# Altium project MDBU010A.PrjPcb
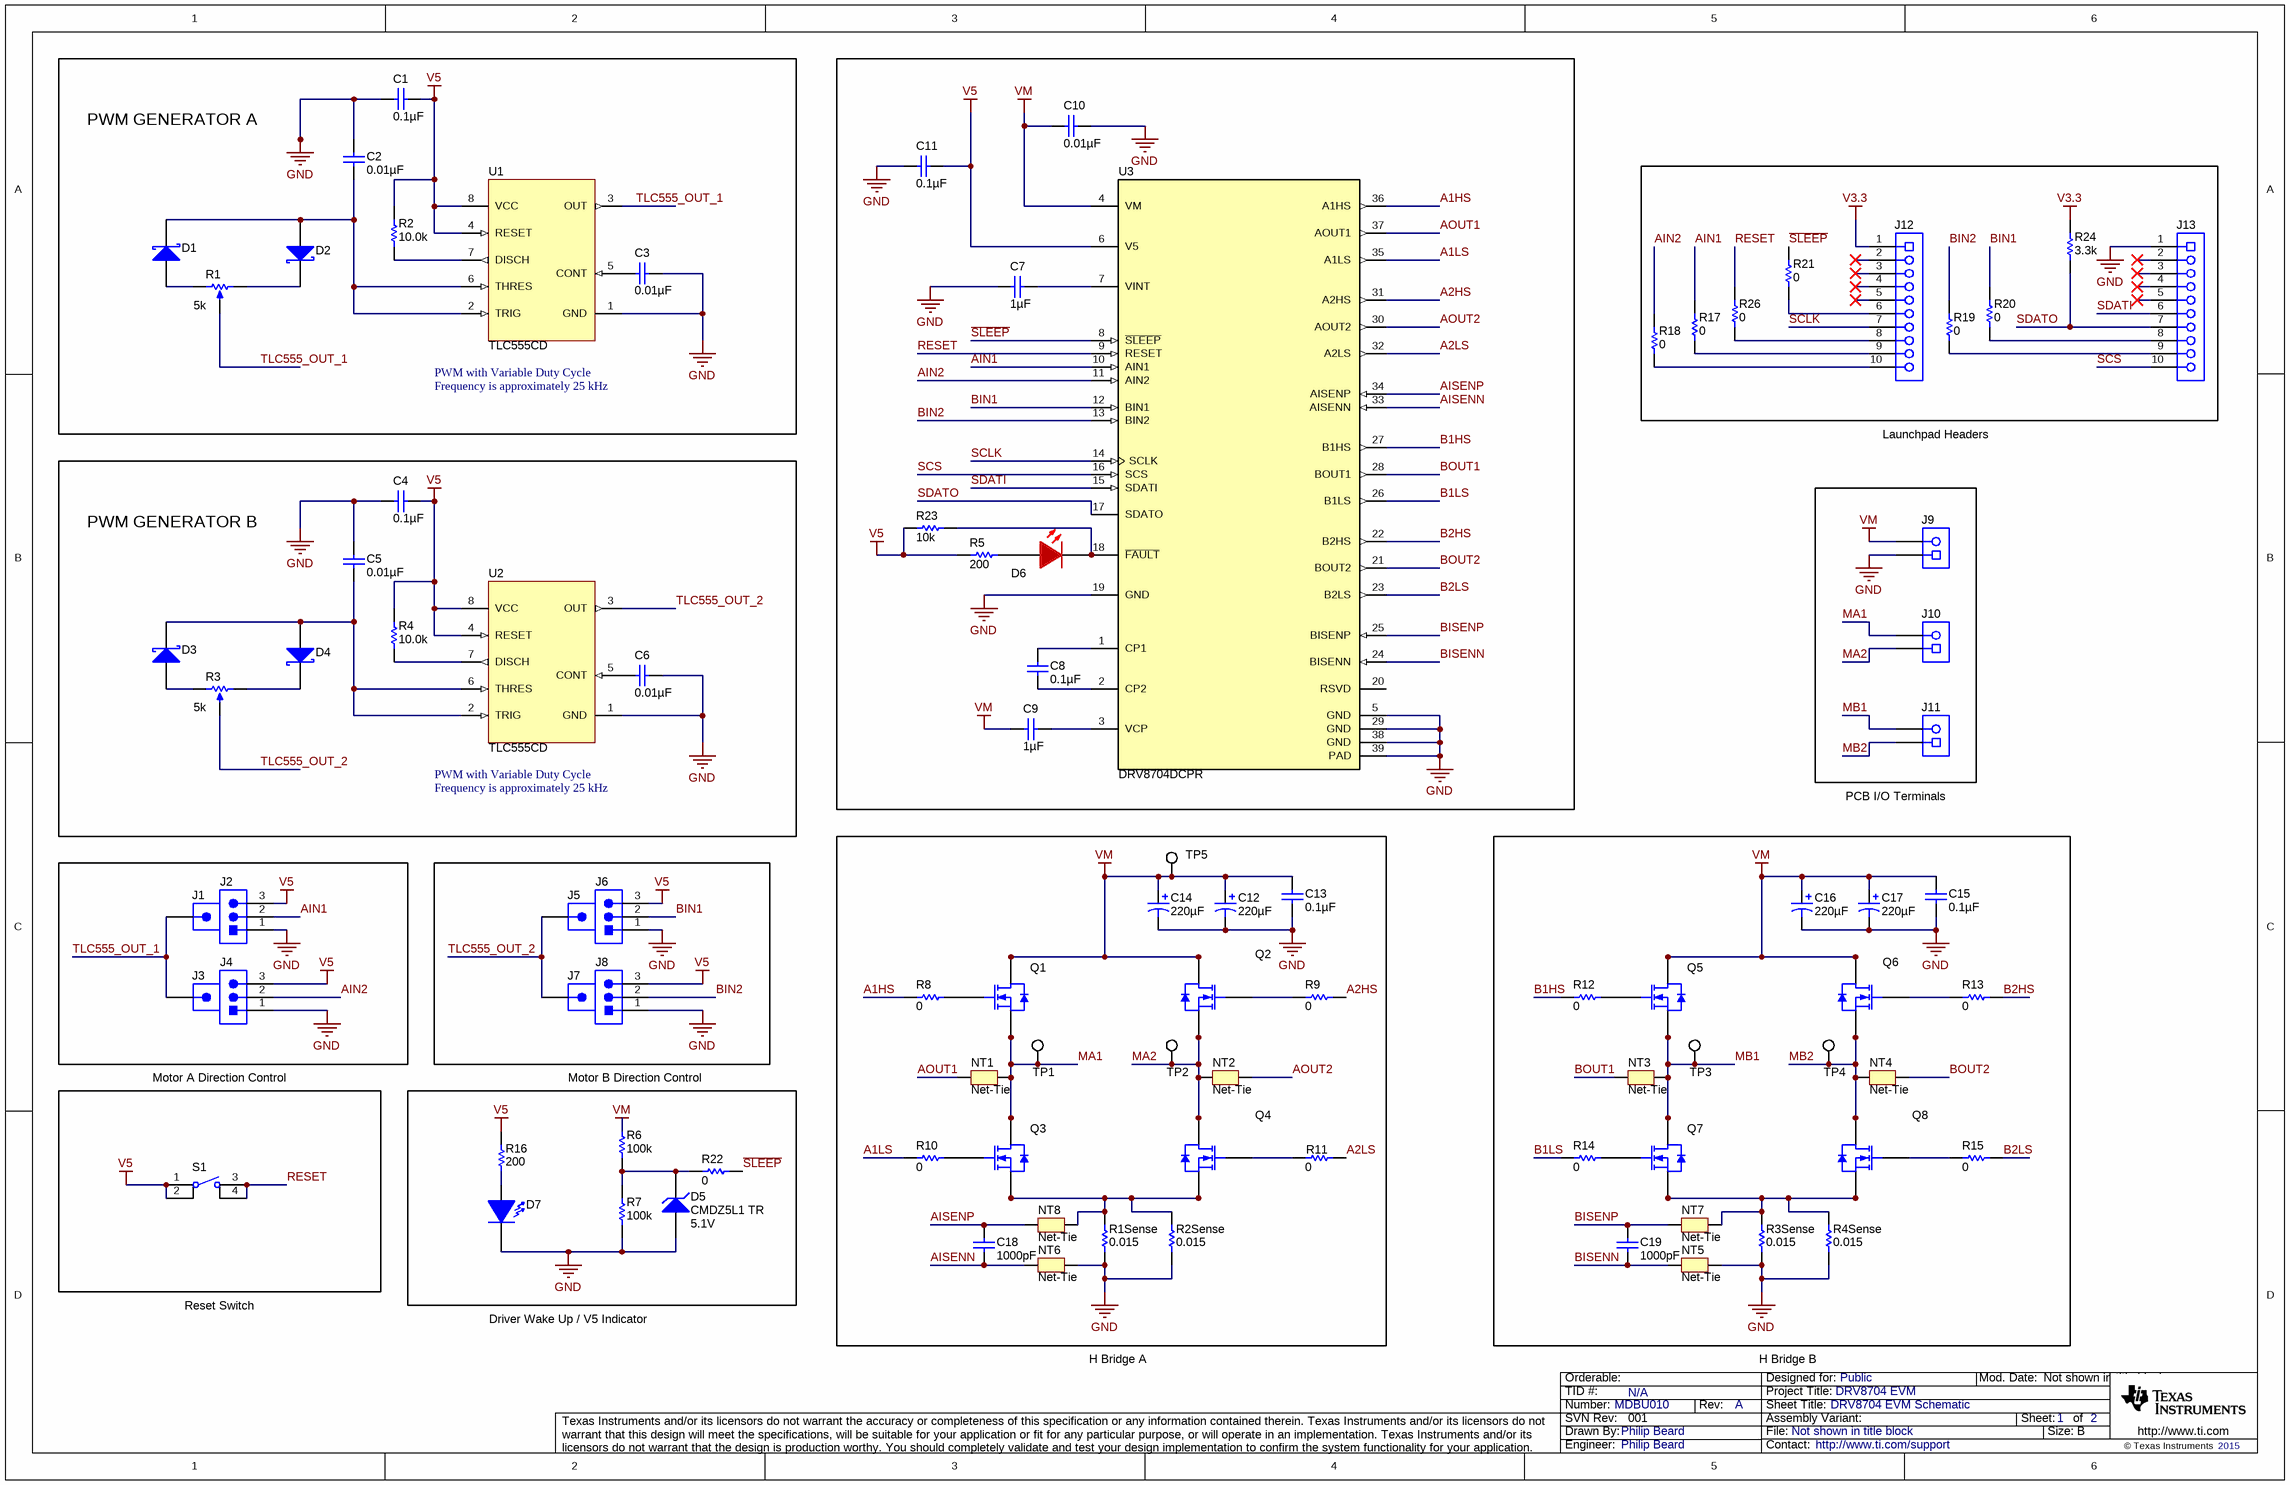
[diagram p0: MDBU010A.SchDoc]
CopyrightYear: 2015; PCB_Layout: Philip Beard; PCB_Rev: A; PRJ_Customer: Public; PRJ_Engineer: Philip Beard; PRJ_Number: MDBU010; PRJ_Title: DRV8704 EVM; SCH_Rev: A; TechSupport: http://www.ti.com/support; TID: N/A
2 sheets, 106 parts. Net scope: global (net labels, ports and power ports of the same name join across sheets).
Board file: MDBU010A.PcbDoc
Sheets:
  MDBU010A.SchDoc
  MDBU010A_Hardware.SchDoc

## Sheet MDBU010A.SchDoc: DRV8704 EVM Schematic
size 431 x 279 mm; VersionControl_RevNumber: 001; Date: Not shown in title block; ApprovedBy: Not shown in title block; CheckedBy: Not shown in title block; Author: Not shown in title block; CompanyName: Not shown in title block; DrawnBy: Philip Beard; Engineer: Not shown in title block; Organization: Not shown in title block; Address1: Not shown in title block; Address2: Not shown in title block; Address3: Not shown in title block; Address4: Not shown in title block; DocumentNumber: 001; Revision: Use project parameter SCH_Rev; SheetNumber: 1; SheetTotal: 2; PageSetup: Record=PageOptions¦CenterHorizontal=True¦CenterVertical=True¦PrintScale=1.00¦XCorrection=1.00¦YCorrection=1.00¦PrintKind=0¦BorderSize=5000000¦LeftOffset=0¦BottomOffset=0¦Orientation=2¦PaperLength=1000¦PaperWidth=1000¦Scale=100¦PaperSource=15¦PrintQuality=600¦MediaType=1¦DitherType=10¦PaperKind=Letter¦PrintScaleMode=1

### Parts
C1  ValueDisplayed: 0.1µF  [0603L]  (hidden comment: C0603C104M4RACTU)
C2  ValueDisplayed: 0.01µF  [0402L]  (hidden comment: GCM155R71E103KA37D)
C3  ValueDisplayed: 0.01µF  [0603L]  (hidden comment: C0603X103K5RACTU)
C4  ValueDisplayed: 0.1µF  [0603L]  (hidden comment: C0603C104M4RACTU)
C5  ValueDisplayed: 0.01µF  [0402L]  (hidden comment: GCM155R71E103KA37D)
C6  ValueDisplayed: 0.01µF  [0603L]  (hidden comment: C0603X103K5RACTU)
C7  ValueDisplayed: 1µF  [0603L]  (hidden comment: EMK107B7105KA-T)
C8  ValueDisplayed: 0.1µF  [0805_HV]  (hidden comment: GRM21BR71H104KA01L)
C9  ValueDisplayed: 1µF  [0402L]  (hidden comment: EMK105BJ105KVHF)
C10  ValueDisplayed: 0.01µF  [0402L]  (hidden comment: C0402C103J5RACTU)
C11  ValueDisplayed: 0.1µF  [0402L]  (hidden comment: GRM155R61A104KA01D)
C12  ValueDisplayed: 220µF  [SM_RADIAL_H13]  (hidden comment: EEE-TK1J221AQ)
C13  ValueDisplayed: 0.1µF  [0402L]  (hidden comment: C1005X7R1H104K050BB)
C14  ValueDisplayed: 220µF  [SM_RADIAL_H13]  (hidden comment: EEE-TK1J221AQ)
C15  ValueDisplayed: 0.1µF  [0402L]  (hidden comment: C1005X7R1H104K050BB)
C16  ValueDisplayed: 220µF  [SM_RADIAL_H13]  (hidden comment: EEE-TK1J221AQ)
C17  ValueDisplayed: 220µF  [SM_RADIAL_H13]  (hidden comment: EEE-TK1J221AQ)
C18  ValueDisplayed: 1000pF  [0402L]  (hidden comment: C1005C0G1E102J)
C19  ValueDisplayed: 1000pF  [0402L]  (hidden comment: C1005C0G1E102J)
D1  MSS1P4-M3/89A  [MicroSMP]  (value not drawn)
D2  MSS1P4-M3/89A  [MicroSMP]  (value not drawn)
D3  MSS1P4-M3/89A  [MicroSMP]  (value not drawn)
D4  MSS1P4-M3/89A  [MicroSMP]  (value not drawn)
D5  CMDZ5L1 TR  value 5.1V  [sod-323]
D6  150080SS75000  [WL-SMCW_RED_0805]  (value not drawn)
D7  150060VS75000  [WL-SMCW_GREEN]  (value not drawn)
J1  PEC01SAAN  [Sullins_PEC01SAAN]  (value not drawn)
J2  PEC03SAAN  [CONN_PEC03SAAN]  (value not drawn)
J3  PEC01SAAN  [Sullins_PEC01SAAN]  (value not drawn)
J4  PEC03SAAN  [CONN_PEC03SAAN]  (value not drawn)
J5  PEC01SAAN  [Sullins_PEC01SAAN]  (value not drawn)
J6  PEC03SAAN  [CONN_PEC03SAAN]  (value not drawn)
J7  PEC01SAAN  [Sullins_PEC01SAAN]  (value not drawn)
J8  PEC03SAAN  [CONN_PEC03SAAN]  (value not drawn)
J9  691 101 710 002  [Wurth_691101710002]  (value not drawn)
J10  691 101 710 002  [Wurth_691101710002]  (value not drawn)
J11  691 101 710 002  [Wurth_691101710002]  (value not drawn)
J12  SSW-110-23-F-S  [CONN_SSW-110-23-F-S]  (value not drawn)
J13  SSW-110-23-F-S  [CONN_SSW-110-23-F-S]  (value not drawn)
NT1  Net-Tie  [Net-Tie_10milWide_30milLong]  (net tie, no BOM)
NT2  Net-Tie  [Net-Tie_10milWide_30milLong]  (net tie, no BOM)
NT3  Net-Tie  [Net-Tie_10milWide_30milLong]  (net tie, no BOM)
NT4  Net-Tie  [Net-Tie_10milWide_30milLong]  (net tie, no BOM)
NT5  Net-Tie  [Net-Tie_10milWide_30milLong]  (net tie, no BOM)
NT6  Net-Tie  [Net-Tie_10milWide_30milLong]  (net tie, no BOM)
NT7  Net-Tie  [Net-Tie_10milWide_30milLong]  (net tie, no BOM)
NT8  Net-Tie  [Net-Tie_10milWide_30milLong]  (net tie, no BOM)
Q1  CSD18540Q5B  [TRANS_NexFET_Q5B]  (value not drawn)
Q2  CSD18540Q5B  [TRANS_NexFET_Q5B]  (value not drawn)
Q3  CSD18540Q5B  [TRANS_NexFET_Q5B]  (value not drawn)
Q4  CSD18540Q5B  [TRANS_NexFET_Q5B]  (value not drawn)
Q5  CSD18540Q5B  [TRANS_NexFET_Q5B]  (value not drawn)
Q6  CSD18540Q5B  [TRANS_NexFET_Q5B]  (value not drawn)
Q7  CSD18540Q5B  [TRANS_NexFET_Q5B]  (value not drawn)
Q8  CSD18540Q5B  [TRANS_NexFET_Q5B]  (value not drawn)
R1  value 5k  [BOURNS_3386P]  (hidden comment: 3386P-1-502LF)
R1Sense  ValueDisplayed: 0.015  [2512]  (hidden comment: CSRN2512FK15L0)
R2  ValueDisplayed: 10.0k  [0603L]  (hidden comment: ERJ-3EKF1002V)
R2Sense  ValueDisplayed: 0.015  [2512]  (hidden comment: CSRN2512FK15L0)
R3  value 5k  [BOURNS_3386P]  (hidden comment: 3386P-1-502LF)
R3Sense  ValueDisplayed: 0.015  [2512]  (hidden comment: CSRN2512FK15L0)
R4  ValueDisplayed: 10.0k  [0603L]  (hidden comment: ERJ-3EKF1002V)
R4Sense  ValueDisplayed: 0.015  [2512]  (hidden comment: CSRN2512FK15L0)
R5  ValueDisplayed: 200  [0402L]  (hidden comment: CRCW0402200RFKED)
R6  ValueDisplayed: 100k  [0402L]  (hidden comment: CRCW0402100KJNED)
R7  ValueDisplayed: 100k  [0402L]  (hidden comment: CRCW0402100KJNED)
R8  ValueDisplayed: 0  [0402L]  (hidden comment: CRCW04020000Z0ED)
R9  ValueDisplayed: 0  [0402L]  (hidden comment: CRCW04020000Z0ED)
R10  ValueDisplayed: 0  [0402L]  (hidden comment: CRCW04020000Z0ED)
R11  ValueDisplayed: 0  [0402L]  (hidden comment: CRCW04020000Z0ED)
R12  ValueDisplayed: 0  [0402L]  (hidden comment: CRCW04020000Z0ED)
R13  ValueDisplayed: 0  [0402L]  (hidden comment: CRCW04020000Z0ED)
R14  ValueDisplayed: 0  [0402L]  (hidden comment: CRCW04020000Z0ED)
R15  ValueDisplayed: 0  [0402L]  (hidden comment: CRCW04020000Z0ED)
R16  ValueDisplayed: 200  [0402L]  (hidden comment: CRCW0402200RFKED)
R17  ValueDisplayed: 0  [0402L]  (hidden comment: CRCW04020000Z0ED)
R18  ValueDisplayed: 0  [0402L]  (hidden comment: CRCW04020000Z0ED)
R19  ValueDisplayed: 0  [0402L]  (hidden comment: CRCW04020000Z0ED)
R20  ValueDisplayed: 0  [0402L]  (hidden comment: CRCW04020000Z0ED)
R21  ValueDisplayed: 0  [0402L]  (hidden comment: CRCW04020000Z0ED)
R22  ValueDisplayed: 0  [0402L]  (hidden comment: CRCW04020000Z0ED)
R23  ValueDisplayed: 10k  [0402L]  (hidden comment: CRCW040210K0JNED)
R24  ValueDisplayed: 3.3k  [0402L]  (hidden comment: CRCW04023K30JNED)
R26  ValueDisplayed: 0  [0402L]  (hidden comment: CRCW04020000Z0ED)
S1  4-1437565-1  [SW_FSM4JSMA]  (value not drawn)
TP1  5016  [Testpoint_Keystone_Compact]  (value not drawn)
TP2  5016  [Testpoint_Keystone_Compact]  (value not drawn)
TP3  5016  [Testpoint_Keystone_Compact]  (value not drawn)
TP4  5016  [Testpoint_Keystone_Compact]  (value not drawn)
TP5  5016  [Testpoint_Keystone_Compact]  (value not drawn)
U1  TLC555CD  [D0008A_L]
U2  TLC555CD  [D0008A_L]
U3  DRV8704DCPR  [DCP0038A_N]

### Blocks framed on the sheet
PWM GENERATOR A: C1-C3 D1 D2 R1 R2 U1
PWM GENERATOR B: C4-C6 D3 D4 R3 R4 U2
Motor A Direction Control: S1
Motor B Direction Control: D5 D7 R6 R7 R16 R22

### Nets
GND: C1.1 C2.1 C3.1 C4.1 C5.1 C6.1 C7.2 C10.1 C11.2 C12.2(-) C13.2 C14.2(-) C15.2 C16.2(-) C17.2(-) D5.2(A) D7.1(K) J2.1 J4.1 J6.1 J8.1 J9.1 J13.1 NT5.2 NT6.2 R1Sense.1 R2Sense.1 R3Sense.1 R4Sense.1 R7.1 U1.1(GND) U2.1(GND) U3.5(GND) U3.19(GND) U3.29(GND) U3.38(GND) U3.39(PAD)
V3.3: J12.1 R24.2
V5: C1.2 C4.2 C11.1 J2.3 J4.3 J6.3 J8.3 R2.2 R4.2 R5.1 R16.2 R23.2 S1.1 S1.2 U1.4(RESET) U1.8(VCC) U2.4(RESET) U2.8(VCC) U3.6(V5)
VM: C9.2 C10.2 C12.1(+) C13.1 C14.1(+) C15.1 C16.1(+) C17.1(+) J9.2 Q1.5(D) Q1.6(D) Q1.7(D) Q1.8(D) Q2.5(D) Q2.6(D) Q2.7(D) Q2.8(D) Q5.5(D) Q5.6(D) Q5.7(D) Q5.8(D) Q6.5(D) Q6.6(D) Q6.7(D) Q6.8(D) R6.2 TP5.1 U3.4(VM)
~{SLEEP}: R21.2 R22.1 U3.8(~{SLEEP})
A1HS: R8.1 U3.36(A1HS)
A1LS: R10.1 U3.35(A1LS)
A2HS: R9.2 U3.31(A2HS)
A2LS: R11.2 U3.32(A2LS)
AIN1: J2.2 R17.2 U3.10(AIN1)
AIN2: J4.2 R18.2 U3.11(AIN2)
AISENN: C18.2 NT6.1 U3.33(AISENN)
AISENP: C18.1 NT8.1 U3.34(AISENP)
AOUT1: NT1.1 U3.37(AOUT1)
AOUT2: NT2.2 U3.30(AOUT2)
B1HS: R12.1 U3.27(B1HS)
B1LS: R14.1 U3.26(B1LS)
B2HS: R13.2 U3.22(B2HS)
B2LS: R15.2 U3.23(B2LS)
BIN1: J6.2 R20.2 U3.12(BIN1)
BIN2: J8.2 R19.2 U3.13(BIN2)
BISENN: C19.2 NT5.1 U3.24(BISENN)
BISENP: C19.1 NT7.1 U3.25(BISENP)
BOUT1: NT3.1 U3.28(BOUT1)
BOUT2: NT4.2 U3.21(BOUT2)
MA1: J10.2 NT1.2 Q1.1(S) Q1.2(S) Q1.3(S) Q3.5(D) Q3.6(D) Q3.7(D) Q3.8(D) TP1.1
MA2: J10.1 NT2.1 Q2.1(S) Q2.2(S) Q2.3(S) Q4.5(D) Q4.6(D) Q4.7(D) Q4.8(D) TP2.1
MB1: J11.2 NT3.2 Q5.1(S) Q5.2(S) Q5.3(S) Q7.5(D) Q7.6(D) Q7.7(D) Q7.8(D) TP3.1
MB2: J11.1 NT4.1 Q6.1(S) Q6.2(S) Q6.3(S) Q8.5(D) Q8.6(D) Q8.7(D) Q8.8(D) TP4.1
RESET: R26.2 S1.3 S1.4 U3.9(RESET)
SCLK: J12.7 U3.14(SCLK)
SCS: J13.10 U3.16(SCS)
SDATI: J13.6 U3.15(SDATI)
SDATO: J13.7 R24.1 U3.17(SDATO)
TLC555_OUT_1: J1.1 J3.1 R1.2(WIPER) U1.3(OUT)
TLC555_OUT_2: J5.1 J7.1 R3.2(WIPER) U2.3(OUT)
NetC2_2: C2.2 D1.1(K) D2.2(A) U1.2(TRIG) U1.6(THRES)
NetC3_2: C3.2 U1.5(CONT)
NetC5_2: C5.2 D3.1(K) D4.2(A) U2.2(TRIG) U2.6(THRES)
NetC6_2: C6.2 U2.5(CONT)
NetC7_1: C7.1 U3.7(VINT)
NetC8_1: C8.1 U3.2(CP2)
NetC8_2: C8.2 U3.1(CP1)
NetC9_1: C9.1 U3.3(VCP)
NetD1_2: D1.2(A) R1.1(CCW)
NetD2_1: D2.1(K) R1.3(CW)
NetD3_2: D3.2(A) R3.1(CCW)
NetD4_1: D4.1(K) R3.3(CW)
NetD5_1: D5.1(K) R6.1 R7.2 R22.2
NetD6_1: D6.1(K) R23.1 U3.18(~{FAULT})
NetD6_2: D6.2(A) R5.2
NetD7_2: D7.2(A) R16.1
NetJ12_6: J12.6 R21.1
NetJ12_8: J12.8 R26.1
NetJ12_9: J12.9 R17.1
NetJ12_10: J12.10 R18.1
NetJ13_8: J13.8 R20.1
NetJ13_9: J13.9 R19.1
NetNT7_2: NT7.2 Q7.1(S) Q7.2(S) Q7.3(S) Q8.1(S) Q8.2(S) Q8.3(S) R3Sense.2 R4Sense.2
NetNT8_2: NT8.2 Q3.1(S) Q3.2(S) Q3.3(S) Q4.1(S) Q4.2(S) Q4.3(S) R1Sense.2 R2Sense.2
NetQ1_4: Q1.4(G) R8.2
NetQ2_4: Q2.4(G) R9.1
NetQ3_4: Q3.4(G) R10.2
NetQ4_4: Q4.4(G) R11.1
NetQ5_4: Q5.4(G) R12.2
NetQ6_4: Q6.4(G) R13.1
NetQ7_4: Q7.4(G) R14.2
NetQ8_4: Q8.4(G) R15.1
NetR2_1: R2.1 U1.7(DISCH)
NetR4_1: R4.1 U2.7(DISCH)

Not connected (* = marked no-connect by the designer): J12 2* 3* 4* 5*; J13 2* 3* 4* 5*; U3 20(RSVD)

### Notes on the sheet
- PWM with Variable Duty Cycle
- Frequency is approximately 25 kHz
- Launchpad Headers
- (near J11) PCB I/O Terminals
- Reset Switch
- Driver Wake Up / V5 Indicator
- H Bridge A
- H Bridge B

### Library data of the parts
C1 C4 = C0603C104M4RACTU: CAP, CERM, 0.1 µF, 16 V, +/- 20%, X7R, 0603; Manufacturer: Kemet; Value: 0.1uF; Polarized: N; CompType: Capacitor; U/M: EA; Cap_F: 0.0000001; Tolerance_%: 20; Value1: Unknown; VDC_V: 16; Value2: 16V; TaMin_C: -55; TaMax_C: 125; Cap_Case: 0603
C2 C5 = GCM155R71E103KA37D: CAP, CERM, 0.01 µF, 25 V, +/- 10%, X7R, 0402; Manufacturer: MuRata; Value: 0.01uF; Polarized: N; CompType: Capacitor; U/M: EA; Cap_F: 0.00000001; Tolerance_%: 10; Value1: Unknown; VDC_V: 25; Value2: 25V; TaMin_C: -55; TaMax_C: 125; Cap_Case: 0402; AEC Category: Q200
C3 C6 = C0603X103K5RACTU: CAP, CERM, 0.01 µF, 50 V, +/- 10%, X7R, 0603; Manufacturer: Kemet; Value: 0.01uF; Polarized: N; CompType: Capacitor; U/M: EA; Cap_F: 0.00000001; Tolerance_%: 10; Value1: Unknown; VDC_V: 50; Value2: 50V; TaMin_C: -55; TaMax_C: 125; Cap_Case: 0603
C7 = EMK107B7105KA-T: CAP, CERM, 1 µF, 16 V, +/- 10%, X7R, 0603; Manufacturer: Taiyo Yuden; Polarized: N; CompType: Capacitor; Value: 1uF; U/M: EA; Cap_F: 0.000001; Tolerance_%: 10; Value1: Unknown; VDC_V: 16; Value2: 16V; TaMin_C: -55; TaMax_C: 85; Cap_Case: 0603; AEC Category: Q200
C8 = GRM21BR71H104KA01L: CAP, CERM, 0.1 µF, 50 V, +/- 10%, X7R, 0805; Manufacturer: MuRata; Polarized: N; CompType: Capacitor; Value: 0.1uF; U/M: EA; Cap_F: 0.0000001; Tolerance_%: 10; Value1: Unknown; VDC_V: 50; Value2: 50V; TaMin_C: -55; TaMax_C: 125; Cap_Case: 0805; AEC Category: Q200
C9 = EMK105BJ105KVHF: CAP, CERM, 1 µF, 16 V, +/- 10%, X5R, 0402; Manufacturer: Taiyo Yuden; Polarized: N; CompType: Capacitor; Value: 1uF; U/M: EA; Cap_F: 0.000001; Tolerance_%: 10; Value1: Unknown; VDC_V: 16; Value2: 16V; TaMin_C: -55; TaMax_C: 85; Cap_Case: 0402; AEC Category: Q200
C10 = C0402C103J5RACTU: CAP, CERM, 0.01 µF, 50 V, +/- 5%, X7R, 0402; Manufacturer: Kemet; Polarized: N; CompType: Capacitor; Value: 0.01uF; U/M: EA; Cap_F: 0.00000001; Tolerance_%: 5; Value1: Unknown; VDC_V: 50; Value2: 50V; TaMin_C: -55; TaMax_C: 125; Cap_Case: 0402; AEC Category: Q200
C11 = GRM155R61A104KA01D: CAP, CERM, 0.1 µF, 10 V, +/- 10%, X5R, 0402; Manufacturer: MuRata; Polarized: N; CompType: Capacitor; Value: 0.1uF; U/M: EA; Cap_F: 0.0000001; Tolerance_%: 10; Value1: Unknown; Value2: 10V; TaMin_C: -55; TaMax_C: 85; Cap_Case: 0402; AEC Category: Q200
C12 C14 C16 C17 = EEE-TK1J221AQ: CAP, AL, 220 µF, 63 V, +/- 20%, 0.26 ohm, AEC-Q200 Grade 1, SMD; Manufacturer: Panasonic; Polarized: Y; CompType: Capacitor; Value: 220uF; U/M: EA; Cap_F: 0.00022; Tolerance_%: 20; VDC_V: 63; Value2: 63V; ESR_ohm: 0.26; IRMS_A: 0.35; TaMin_C: -40; TaMax_C: 125; Cap_Case: 12.5x13.5; AEC Category: Q200; AEC Grade: 1
C13 C15 = C1005X7R1H104K050BB: CAP, CERM, 0.1 µF, 50 V, +/- 10%, X7R, 0402; Manufacturer: TDK; Polarized: N; CompType: Capacitor; Value: 0.1uF; U/M: EA; Cap_F: 0.0000001; Tolerance_%: 10; Value1: Unknown; VDC_V: 50; Value2: 50V; TaMin_C: -55; TaMax_C: 125; Cap_Case: 0402; AEC Category: Q200
C18 C19 = C1005C0G1E102J: CAP, CERM, 1000 pF, 25 V, +/- 5%, C0G/NP0, 0402; Manufacturer: TDK; Polarized: N; CompType: Capacitor; Value: 1000pF; U/M: EA; Cap_F: 0.000000001; Tolerance_%: 5; Value1: Unknown; VDC_V: 25; Value2: 25V; TaMin_C: -55; TaMax_C: 125; Cap_Case: 0402; AEC Category: Q200
D1-D4 = MSS1P4-M3/89A: Diode, Schottky, 40 V, 1 A, MicroSMP; Manufacturer: Vishay-Siliconix; Value: 40V; U/M: EA; Vf_V: 0.55; Value1: 1A; Value2: 0.55V; Io_A: 1; Vr_V: 40; TJmax_C: 150
D5 = CMDZ5L1 TR: Diode, Zener, 5.1 V, 250 mW, SOD-323; Manufacturer: Central Semiconductor; U/M: EA; Power_W: 0.25; Vz_V: 5.1; Value1: 0.25W; RJA_CperW: 500; AEC Category: Q101; SymbolCreator: a0412235
D6 = 150080SS75000: LED, Red, SMD; Manufacturer: Wurth Elektronik; SymbolCreator: Altium; Type: AlInGaP; Vf_V: 1.9; Value2: 1.9V; Io_A: 0.03; Vr_V: 5; Ir_A: 2.5e-005; Tjmax_C: 85; Power_TotalModule: 0.072; Value1: 0.072W; Angle: 140; U/M: EA
D7 = 150060VS75000: LED, Green, SMD; Manufacturer: Wurth Elektronik; Type: AlInGaP; Vf_V: 2; Value2: 2V; Io_A: 0.02; Value1: W; U/M: EA
J1 J3 J5 J7 = PEC01SAAN: Header, 1x1, Tin, TH; Manufacturer: Sullins Connector Solutions; SymbolCreator: a0412235; U/M: EA
J2 J4 J6 J8 = PEC03SAAN: Header, 100mil, 3x1, Tin, TH; Manufacturer: Sullins Connector Solutions; SymbolCreator: a0799628; U/M: EA
J9-J11 = 691 101 710 002: Terminal Block, 5 mm, 2x1, Tin, TH; Manufacturer: Wurth Elektronik; SymbolCreator: a0412235; U/M: EA
J12 J13 = SSW-110-23-F-S: Connector, Receptacle, 100mil, 10x1, Gold plated, TH; Manufacturer: Samtec; SymbolCreator: a0411947; U/M: EA
NT1-NT8 = Net-Tie: Single point connection between nets.; SymbolCreator: codlsc
Q1-Q8 = CSD18540Q5B: MOSFET, N-CH, 60 V, 28 A, SON 5x6mm; Manufacturer: Texas Instruments; Alternate Manufacturer: None; U/M: EA; ChType: N; Value: 60V; VdsMax_V: 60; Value1: 0.0033 ohm; Rdson45_ohm: 0.0033; Value2: 41 nC; QgTyp_nC: 41; Vgs_V: 20; IdsMax_A: 28; AEC Category: Q101
R1 R3 = 3386P-1-502LF: TRIMMER, 5k ohm, 0.5W, TH; Manufacturer: Bourns; Sim Note: Enter the Resistance value and the set point into parameter fields.; SymbolCreator: a0412235
R1Sense R2Sense R3Sense R4Sense = CSRN2512FK15L0: RES, 0.015, 1%, 2 W, 2512; Manufacturer: Stackpole Electronics Inc; CompType: Resistor; Value: 0.015; Value_Code: R015; Tolerance_%: 1; Power_W: 2; Value2: 2W; TempCo: 200 ppm/C; EIA_Code: E96; U/M: EA; AEC Category: Q200
R2 R4 = ERJ-3EKF1002V: RES, 10.0 k, 1%, 0.1 W, 0603; Manufacturer: Panasonic; Value: 10.0k; CompType: Resistor; Res_ohm: 10000; Value_Code: 10k0; Tolerance_%: 1; Power_W: 0.1; Value2: 0.1W; VDC_V: 75; TempCo: 100 ppm/C; EIA_Code: E96; U/M: EA
R5 R16 = CRCW0402200RFKED: RES, 200, 1%, 0.063 W, 0402; Manufacturer: Vishay-Dale; CompType: Resistor; Value: 200; Value_Code: 200R; Tolerance_%: 1; Power_W: 0.063; Value2: 0.063W; VDC_V: 50; TempCo: 100 ppm/C; EIA_Code: E96; U/M: EA
R6 R7 = CRCW0402100KJNED: RES, 100 k, 5%, 0.063 W, 0402; Manufacturer: Vishay-Dale; CompType: Resistor; Value: 100k; Res_ohm: 100000; Tolerance_%: 5; Power_W: 0.063; Value2: 0.063W; VDC_V: 50; TempCo: 200 ppm/C; EIA_Code: E24; U/M: EA
R8-R15 R17-R22 R26 = CRCW04020000Z0ED: RES, 0, 5%, 0.063 W, 0402; Manufacturer: Vishay-Dale; CompType: Resistor; Value: 0; Value_Code: 0000; Tolerance_%: 5; Power_W: 0.063; Value2: 0.063W; VDC_V: 50; TempCo: 200 ppm/C; EIA_Code: E24; U/M: EA
R23 = CRCW040210K0JNED: RES, 10 k, 5%, 0.063 W, 0402; Manufacturer: Vishay-Dale; CompType: Resistor; Value: 10k; Res_ohm: 10000; Value_Code: 10k0; Tolerance_%: 5; Power_W: 0.063; Value2: 0.063W; VDC_V: 50; TempCo: 200 ppm/C; EIA_Code: E24; U/M: EA
R24 = CRCW04023K30JNED: RES, 3.3 k, 5%, 0.063 W, 0402; Manufacturer: Vishay-Dale; CompType: Resistor; Value: 3.3k; Res_ohm: 3300; Value_Code: 3k30; Tolerance_%: 5; Power_W: 0.063; Value2: 0.063W; VDC_V: 50; TempCo: 200 ppm/C; EIA_Code: E24; U/M: EA
S1 = 4-1437565-1: Switch, Tactile, SPST-NO, 0.05A, 12V, SMT; Manufacturer: TE Connectivity; SymbolCreator: a0412235; VDC_V: 12; SwitchFunction: Off-Mom; PositionCount: 1; CurrentRating_mA: 50
TP1-TP5 = 5016: Test Point, Compact, SMT; Manufacturer: Keystone; CompType: Test Point Loop; U/M: EA
U1 U2 = TLC555CD: LinCMOS Timer, D0008A; Manufacturer: Texas Instruments; SymbolCreator: a0799628; CompType: IC; U/M: EA
U3 = DRV8704DCPR: 52-V Dual H-Bridge PWM Gate Driver, DCP0038A; Manufacturer: Texas Instruments; SymbolCreator: a0411947; CompType: IC; U/M: EA

## Sheet MDBU010A_Hardware.SchDoc
size 431 x 279 mm; Date: Not shown in title block; ApprovedBy: Not shown in title block; CheckedBy: Not shown in title block; Author: Not shown in title block; CompanyName: Not shown in title block; Engineer: Not shown in title block; Organization: Not shown in title block; Address1: Not shown in title block; Address2: Not shown in title block; Address3: Not shown in title block; Address4: Not shown in title block; DocumentNumber: 1; Revision: Use project parameter SCH_Rev; SheetNumber: 2; SheetTotal: 2; PageSetup: Record=PageOptions¦CenterHorizontal=True¦CenterVertical=True¦PrintScale=1.00¦XCorrection=1.00¦YCorrection=1.00¦PrintKind=0¦BorderSize=5000000¦LeftOffset=0¦BottomOffset=0¦Orientation=2¦PaperLength=1000¦PaperWidth=1000¦Scale=100¦PaperSource=15¦PrintQuality=600¦MediaType=1¦DitherType=10¦PaperKind=Letter¦PrintScaleMode=1
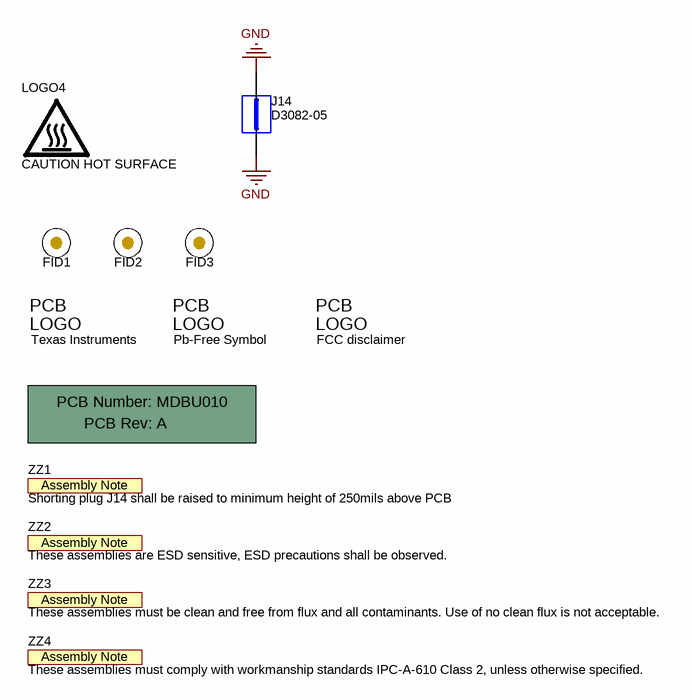
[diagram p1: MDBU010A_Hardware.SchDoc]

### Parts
!PCB  Printed Circuit Board  (value not drawn)  (mechanical)
FID1  Fiducial  [Fiducial10-20]  (value not drawn)
FID2  Fiducial  [Fiducial10-20]  (value not drawn)
FID3  Fiducial  [Fiducial10-20]  (value not drawn)
J14  D3082-05  [Harwin_D3082-05]
Logo1  Texas Instruments  [TI_Stacked_Overlay_Small]  (no BOM)
Logo2  Pb-Free Symbol  [Pb-Free_Overlay_Medium]  (no BOM)
Logo3  FCC disclaimer  [FCC_disclaimer]  (no BOM)
LOGO4  CAUTION HOT SURFACE  [IEC_HotSurface_Small]  (no BOM)
ZZ1  Shorting plug J14 shall be raised to minimum height of 250mils above PCB  [AssemblyNote]  (no BOM)
ZZ2  These assemblies are ESD sensitive, ESD precautions shall be observed.  [AssemblyNote]  (no BOM)
ZZ3  These assemblies must be clean and free from flux and all contaminants. Use of no clean flux is not acceptable.  [AssemblyNote]  (no BOM)
ZZ4  These assemblies must comply with workmanship standards IPC-A-610 Class 2, unless otherwise specified.  [AssemblyNote]  (no BOM)

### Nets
GND: J14.1 J14.2

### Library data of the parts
!PCB = PCB: Manufacturer: Any; PartNumber: MDBU010; SymbolCreator: a0412235
FID1-FID3 = Fiducial: Fiducial mark.  There is nothing to buy or mount.; SymbolCreator: codlsc
J14 = D3082-05: 1mm Uninsulated Shorting Plug, 10.16mm spacing, TH; Manufacturer: Harwin; SymbolCreator: a0799628; CompType: Jumper Wire; U/M: EA
Logo1 = TI_Logo: Texas Instrument Corporate Signature; SymbolCreator: codlsc
Logo2 = Pb-Free: SymbolCreator: a0412235
Logo3 = FCC_disclaimer: SymbolCreator: codlsc
LOGO4 = IEC_HotSurface: IEC 61010-1 Hot Surface Warning; SymbolCreator: a0412235
ZZ1-ZZ4 = AssemblyNote: SymbolCreator: codlsc

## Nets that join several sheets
GND: MDBU010A (37 pins), MDBU010A_Hardware (J14.1 J14.2)

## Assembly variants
001: not fitted C18 C19 FID1 FID2 FID3 R17 R18 R19 R20 R21 R26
